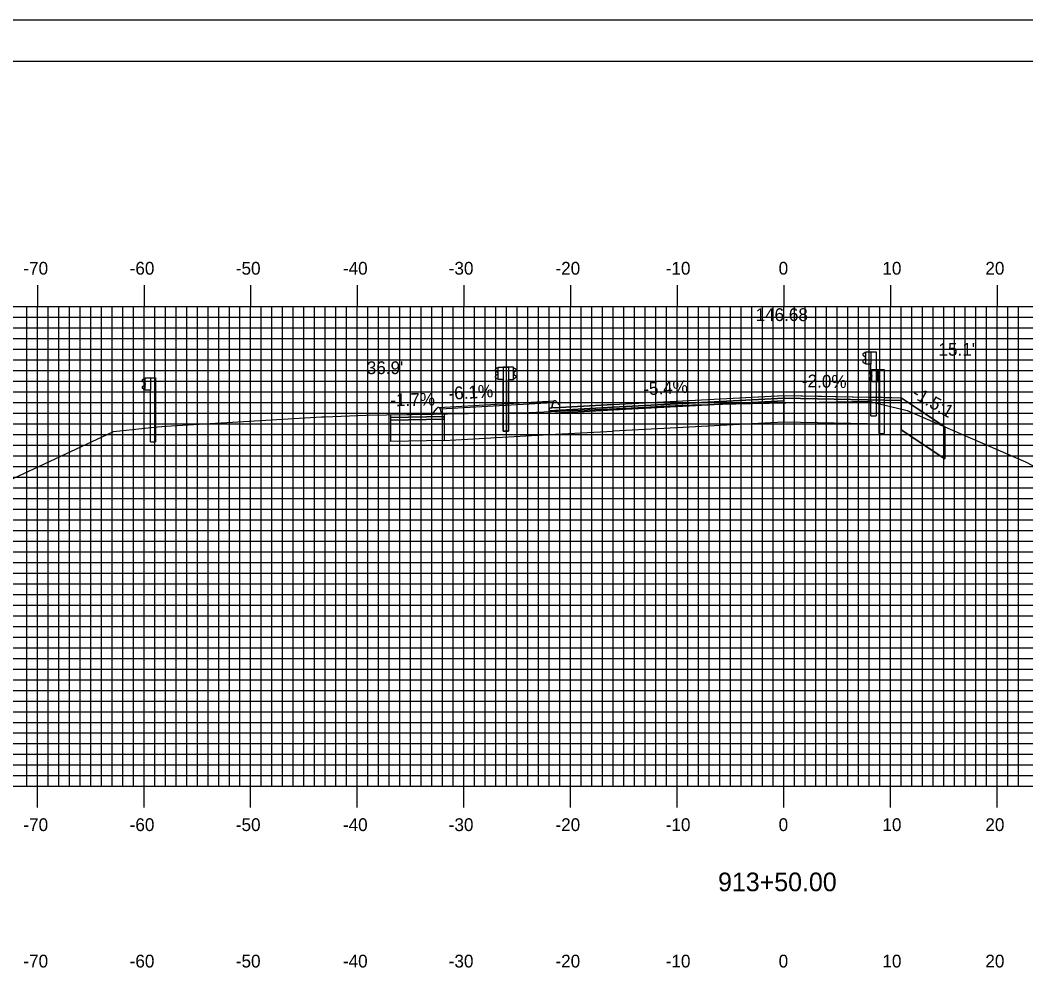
# Model space of a CAD drawing. Extents: x 860258 to 860601, y 364765 to 364985.
# Drawn here: x 860352.3 to 860446.6, y 364895.8 to 364985.2 of the extents above; entities that cross this region are included whole.
import ezdxf

# ---------------------------------------------------------------- set-up
doc = ezdxf.new("R2010")
doc.units = 0
for name, color, linetype in [('ANNOTATION', 7, 'Continuous'), ('BORDER', 7, 'Continuous'), ('D_Curb_Type_3M2_Lt', 7, 'Continuous'), ('D_Curb_Type_3M2_Rt', 7, 'Continuous'), ('D_Guardrail_Beam_Rt', 7, 'Continuous'), ('D_Roadway_Centerline', 7, 'Continuous'), ('D_Roadway_Centerline_Text', 7, 'Continuous'), ('D_Roadway_Edge_Shoulder', 7, 'Continuous'), ('D_Roadway_Edge_TW', 7, 'Continuous'), ('D_Roadway_FinishedGrade', 7, 'Continuous'), ('D_Roadway_Pavement', 7, 'Continuous'), ('D_Roadway_SubGrade', 7, 'Continuous'), ('D_Text_Standard', 7, 'Continuous'), ('H_V ANNOTATION', 7, 'Continuous'), ('M_Guardrail', 7, 'Continuous'), ('M_Roadway_Centerline', 7, 'Continuous'), ('MAJOR', 7, 'Continuous'), ('MINOR', 7, 'Continuous'), ('PATTERNING', 7, 'Continuous'), ('PLOT BOUNDARY', 7, 'Continuous'), ('S_Roadway_Centerline', 7, 'Continuous')]:
    doc.layers.add(name, color=color, linetype=linetype)

msp = doc.modelspace()

# ---------------------------------------------------------------- linework, layer by layer
at = {"layer": 'BORDER'}
msp.add_lwpolyline([(860274.299, 364771.302), (860594.299, 364771.302), (860594.299, 364981.302), (860274.299, 364981.302)], close=True, dxfattribs=at)
at = {"layer": 'D_Curb_Type_3M2_Lt'}
for p, q in [((860402.258, 364949.339), (860402.15, 364948.845)), ((860402.15, 364948.845), (860402.9, 364948.845)), ((860402.394, 364949.468), (860402.398, 364949.468)), ((860402.9, 364949.012), (860402.545, 364949.414)), ((860402.9, 364948.845), (860402.9, 364949.012))]:
    msp.add_line(p, q, dxfattribs=at)
msp.add_arc((860402.42, 364949.304), 0.167, 41.38705, 167.66476, dxfattribs=at)
at = {"layer": 'D_Curb_Type_3M2_Rt'}
for p, q in [((860391.036, 364948.385), (860391.39, 364948.787)), ((860391.678, 364948.712), (860391.786, 364948.218)), ((860391.036, 364948.218), (860391.036, 364948.385)), ((860391.786, 364948.218), (860391.036, 364948.218))]:
    msp.add_line(p, q, dxfattribs=at)
msp.add_arc((860391.515, 364948.677), 0.167, 12.33524, 138.61295, dxfattribs=at)
at = {"layer": 'D_Guardrail_Beam_Rt'}
for p, q in [((860432.17, 364952.403), (860432.857, 364952.403)), ((860432.17, 364951.236), (860432.17, 364952.403)), ((860432.691, 364952.403), (860432.691, 364951.236)), ((860432.795, 364952.403), (860432.795, 364951.236)), ((860432.857, 364952.403), (860433.328, 364952.403)), ((860432.857, 364952.403), (860432.857, 364951.236)), ((860433.328, 364952.403), (860433.328, 364946.403)), ((860432.08, 364952.298), (860431.936, 364952.198)), ((860431.936, 364952.055), (860432.132, 364951.919)), ((860432.132, 364951.72), (860431.936, 364951.584)), ((860431.936, 364951.44), (860432.08, 364951.34)), ((860432.17, 364952.319), (860432.096, 364952.305)), ((860432.166, 364951.854), (860432.166, 364951.784)), ((860432.096, 364951.334), (860432.17, 364951.319)), ((860432.857, 364951.236), (860432.17, 364951.236)), ((860432.837, 364946.403), (860432.837, 364951.236)), ((860432.837, 364946.403), (860433.328, 364946.403))]:
    msp.add_line(p, q, dxfattribs=at)
for centre, major_axis, start_param, end_param in [((860431.987, 364952.126), (-0.0877, 0), 5.323254, 7.243116), ((860431.987, 364951.512), (-0.0877, 0), 5.323254, 7.243116), ((860432.104, 364952.264), (-0.0417, 0), 4.907132, 5.323254), ((860432.087, 364951.854), (0.0789, 0), 0, 0.959931), ((860432.087, 364951.784), (0.0789, 0), 5.323254, 6.283185), ((860432.104, 364951.374), (-0.0417, 0), 0.959931, 1.376053)]:
    msp.add_ellipse(centre, major_axis=major_axis, ratio=0.995501, start_param=start_param, end_param=end_param, dxfattribs=at)
at = {"layer": 'D_Roadway_Centerline'}
for points in [[(860402.9, 364948.845), (860407.898, 364949.115), (860407.899, 364949.115), (860423.887, 364949.979), (860423.9, 364949.979), (860427.436, 364949.908), (860431.899, 364949.819), (860431.9, 364949.819), (860433.145, 364949.794), (860434.9, 364949.759), (860434.906, 364949.756), (860438.999, 364947.028)], [(860387.035, 364948.15), (860390.957, 364948.217), (860391.034, 364948.218), (860391.036, 364948.218)]]:
    msp.add_lwpolyline(points, dxfattribs=at)
at = {"layer": 'D_Roadway_Edge_Shoulder'}
for points in [[(860423.9, 364949.979), (860431.899, 364949.819), (860431.899, 364949.819), (860434.9, 364949.759), (860434.9, 364949.509), (860423.9, 364949.729)], [(860407.899, 364949.115), (860402.9, 364948.845), (860401.9, 364948.791), (860401.9, 364948.541), (860407.899, 364948.865)], [(860387.035, 364948.15), (860391.036, 364948.218), (860392.036, 364948.236), (860392.036, 364947.986), (860387.035, 364947.9)]]:
    msp.add_lwpolyline(points, close=True, dxfattribs=at)
at = {"layer": 'D_Roadway_Edge_TW'}
msp.add_lwpolyline([(860407.899, 364949.115), (860423.9, 364949.979), (860423.9, 364949.729), (860407.899, 364948.865)], close=True, dxfattribs=at)
at = {"layer": 'D_Roadway_FinishedGrade'}
msp.add_line((860434.906, 364949.756), (860434.906, 364946.756), dxfattribs=at)
for points in [[(860434.906, 364949.756), (860436.406, 364948.756), (860438.999, 364947.028)], [(860391.557, 364948.838), (860402.379, 364949.465)], [(860438.999, 364947.028), (860438.999, 364944.028), (860434.906, 364946.756)]]:
    msp.add_lwpolyline(points, dxfattribs=at)
at = {"layer": 'D_Roadway_Pavement'}
for points in [[(860407.899, 364948.865), (860423.9, 364949.729), (860423.9, 364949.479), (860407.899, 364948.615)], [(860407.899, 364948.865), (860401.9, 364948.541), (860401.9, 364948.291), (860407.899, 364948.615)], [(860387.035, 364947.9), (860392.036, 364947.986), (860392.036, 364947.736), (860387.035, 364947.65)]]:
    msp.add_lwpolyline(points, close=True, dxfattribs=at)
msp.add_lwpolyline([(860423.9, 364949.729), (860423.9, 364949.479)], dxfattribs=at)
msp.add_lwpolyline([(860423.9, 364949.729), (860423.9, 364949.479)], dxfattribs=at)
at = {"layer": 'D_Roadway_SubGrade'}
for points in [[(860423.9, 364949.479), (860423.9, 364949.729), (860434.9, 364949.509), (860434.9, 364949.759), (860434.906, 364947.259), (860423.9, 364947.479)], [(860392.036, 364948.236), (860392.036, 364945.736), (860401.9, 364946.291), (860401.9, 364948.291), (860401.9, 364948.541), (860401.9, 364948.791), (860402.141, 364948.804), (860402.247, 364949.29), (860391.685, 364948.678), (860391.784, 364948.232)], [(860407.899, 364948.615), (860401.9, 364948.291), (860401.9, 364948.541), (860401.9, 364946.291), (860407.899, 364946.615)], [(860407.899, 364948.615), (860423.9, 364949.479), (860423.9, 364947.479), (860407.899, 364946.615)], [(860387.035, 364947.65), (860392.036, 364947.736), (860392.036, 364947.986), (860392.036, 364945.736), (860387.035, 364945.65)]]:
    msp.add_lwpolyline(points, close=True, dxfattribs=at)
at = {"layer": 'M_Guardrail'}
for p, q in [((860431.486, 364953.978), (860431.343, 364953.878)), ((860431.343, 364953.735), (860431.538, 364953.598)), ((860431.538, 364953.379), (860431.343, 364953.242)), ((860431.585, 364953.999), (860431.503, 364953.985)), ((860431.572, 364953.534), (860431.572, 364953.443)), ((860431.585, 364954.072), (860432.075, 364954.072)), ((860431.585, 364952.905), (860431.585, 364954.072)), ((860432.075, 364954.072), (860432.566, 364954.072)), ((860432.075, 364954.072), (860432.075, 364952.905)), ((860432.566, 364954.072), (860432.566, 364948.072)), ((860396.998, 364952.53), (860396.854, 364952.43)), ((860397.097, 364952.551), (860397.015, 364952.537)), ((860397.097, 364952.624), (860397.586, 364952.624)), ((860397.097, 364951.458), (860397.097, 364952.624)), ((860397.575, 364952.622), (860397.575, 364946.622)), ((860398.066, 364952.622), (860397.575, 364952.622)), ((860397.586, 364952.624), (860398.078, 364952.624)), ((860397.586, 364952.624), (860397.586, 364951.458)), ((860398.556, 364952.622), (860398.066, 364952.622)), ((860398.066, 364952.622), (860398.066, 364951.455)), ((860398.078, 364952.624), (860398.078, 364946.624)), ((860398.556, 364951.455), (860398.556, 364952.622)), ((860398.556, 364952.549), (860398.638, 364952.534)), ((860398.655, 364952.528), (860398.798, 364952.428)), ((860431.343, 364953.099), (860431.486, 364952.999)), ((860431.503, 364952.993), (860431.585, 364952.978)), ((860432.075, 364952.905), (860431.585, 364952.905)), ((860432.075, 364948.072), (860432.075, 364952.905)), ((860363.908, 364951.533), (860363.765, 364951.433)), ((860364.007, 364951.555), (860363.925, 364951.54)), ((860364.007, 364951.628), (860364.496, 364951.628)), ((860364.007, 364950.461), (860364.007, 364951.628)), ((860364.496, 364951.628), (860364.988, 364951.628)), ((860364.496, 364951.628), (860364.496, 364950.461)), ((860364.988, 364951.628), (860364.988, 364945.628)), ((860396.854, 364952.287), (860397.05, 364952.151)), ((860397.05, 364951.931), (860396.854, 364951.795)), ((860396.854, 364951.652), (860396.998, 364951.552)), ((860397.015, 364951.545), (860397.097, 364951.531)), ((860397.083, 364952.087), (860397.083, 364951.995)), ((860397.586, 364951.458), (860397.097, 364951.458)), ((860397.586, 364946.624), (860397.586, 364951.458)), ((860398.066, 364946.622), (860398.066, 364951.455)), ((860398.066, 364951.455), (860398.556, 364951.455)), ((860398.638, 364951.542), (860398.556, 364951.528)), ((860398.569, 364952.084), (860398.569, 364951.993)), ((860398.798, 364952.284), (860398.603, 364952.148)), ((860398.603, 364951.928), (860398.798, 364951.792)), ((860398.798, 364951.649), (860398.655, 364951.549)), ((860363.765, 364951.29), (860363.96, 364951.154)), ((860363.96, 364950.934), (860363.765, 364950.798)), ((860363.765, 364950.655), (860363.908, 364950.555)), ((860363.925, 364950.548), (860364.007, 364950.534)), ((860363.994, 364951.09), (860363.994, 364950.999)), ((860364.496, 364950.461), (860364.007, 364950.461)), ((860364.496, 364945.628), (860364.496, 364950.461)), ((860432.075, 364948.072), (860432.566, 364948.072)), ((860398.066, 364946.622), (860397.575, 364946.622)), ((860397.586, 364946.624), (860398.078, 364946.624)), ((860364.496, 364945.628), (860364.988, 364945.628))]:
    msp.add_line(p, q, dxfattribs=at)
for centre, major_axis, start_param, end_param in [((860431.393, 364953.806), (-0.0877, 0), 5.323254, 7.243116), ((860431.51, 364953.944), (-0.0417, 0), 4.886922, 5.323254), ((860431.493, 364953.534), (0.0789, 0), 0, 0.959931), ((860431.493, 364953.443), (0.0789, 0), 5.323254, 6.283185), ((860396.905, 364952.359), (-0.0877, 0), 5.323254, 7.243116), ((860397.022, 364952.496), (-0.0417, 0), 4.886922, 5.323254), ((860398.631, 364952.494), (0.0417, 0), 0.959931, 1.396263), ((860398.748, 364952.356), (0.0877, 0), 5.323254, 7.243116), ((860431.393, 364953.171), (-0.0877, 0), 5.323254, 7.243116), ((860431.51, 364953.033), (-0.0417, 0), 0.959931, 1.396263), ((860363.815, 364951.362), (-0.0877, 0), 5.323254, 7.243116), ((860363.932, 364951.499), (-0.0417, 0), 4.886922, 5.323254), ((860396.905, 364951.723), (-0.0877, 0), 5.323254, 7.243116), ((860397.022, 364951.586), (-0.0417, 0), 0.959931, 1.396263), ((860397.005, 364952.087), (0.0789, 0), 0, 0.959931), ((860397.005, 364951.995), (0.0789, 0), 5.323254, 6.283185), ((860398.648, 364952.084), (-0.0789, 0), 5.323254, 6.283185), ((860398.648, 364951.993), (-0.0789, 0), 6.283185, 7.243116), ((860398.631, 364951.583), (0.0417, 0), 4.886922, 5.323254), ((860398.748, 364951.721), (0.0877, 0), 5.323254, 7.243116), ((860363.815, 364950.727), (-0.0877, 0), 5.323254, 7.243116), ((860363.932, 364950.589), (-0.0417, 0), 0.959931, 1.396263), ((860363.915, 364951.09), (0.0789, 0), 0, 0.959931), ((860363.915, 364950.999), (0.0789, 0), 5.323254, 6.283185)]:
    msp.add_ellipse(centre, major_axis=major_axis, ratio=0.995501, start_param=start_param, end_param=end_param, dxfattribs=at)
at = {"layer": 'MAJOR'}
for p, q in [((860353.899, 364960.306), (860353.899, 364958.302)), ((860363.899, 364960.306), (860363.899, 364958.302)), ((860373.899, 364960.306), (860373.899, 364958.302)), ((860383.899, 364960.306), (860383.899, 364958.302)), ((860393.899, 364960.306), (860393.899, 364958.302)), ((860403.899, 364960.306), (860403.899, 364958.302)), ((860413.899, 364960.306), (860413.899, 364958.302)), ((860423.899, 364960.306), (860423.899, 364958.302)), ((860433.899, 364960.306), (860433.899, 364958.302)), ((860443.899, 364960.306), (860443.899, 364958.302)), ((860283.899, 364958.302), (860563.899, 364958.302)), ((860283.899, 364958.302), (860563.899, 364958.302)), ((860353.899, 364913.302), (860353.899, 364958.302)), ((860363.899, 364913.302), (860363.899, 364958.302)), ((860373.899, 364913.302), (860373.899, 364958.302)), ((860383.899, 364913.302), (860383.899, 364958.302)), ((860393.899, 364913.302), (860393.899, 364958.302)), ((860403.899, 364913.302), (860403.899, 364958.302)), ((860413.899, 364913.302), (860413.899, 364958.302)), ((860423.899, 364913.302), (860423.899, 364958.302)), ((860433.899, 364913.302), (860433.899, 364958.302)), ((860443.899, 364913.302), (860443.899, 364958.302)), ((860283.899, 364953.302), (860563.899, 364953.302)), ((860283.899, 364948.302), (860563.899, 364948.302)), ((860283.899, 364943.302), (860563.899, 364943.302)), ((860283.899, 364938.302), (860563.899, 364938.302)), ((860283.899, 364933.302), (860563.899, 364933.302)), ((860283.899, 364928.302), (860563.899, 364928.302)), ((860283.899, 364923.302), (860563.899, 364923.302)), ((860283.899, 364918.302), (860563.899, 364918.302)), ((860283.899, 364913.302), (860563.899, 364913.302)), ((860283.899, 364913.302), (860563.899, 364913.302)), ((860353.899, 364911.298), (860353.899, 364913.302)), ((860363.899, 364911.298), (860363.899, 364913.302)), ((860373.899, 364911.298), (860373.899, 364913.302)), ((860383.899, 364911.298), (860383.899, 364913.302)), ((860393.899, 364911.298), (860393.899, 364913.302)), ((860403.899, 364911.298), (860403.899, 364913.302)), ((860413.899, 364911.298), (860413.899, 364913.302)), ((860423.899, 364911.298), (860423.899, 364913.302)), ((860433.899, 364911.298), (860433.899, 364913.302)), ((860443.899, 364911.298), (860443.899, 364913.302))]:
    msp.add_line(p, q, dxfattribs=at)
at = {"layer": 'MINOR'}
for p, q in [((860352.899, 364913.302), (860352.899, 364958.302)), ((860354.899, 364913.302), (860354.899, 364958.302)), ((860355.899, 364913.302), (860355.899, 364958.302)), ((860356.899, 364913.302), (860356.899, 364958.302)), ((860357.899, 364913.302), (860357.899, 364958.302)), ((860358.899, 364913.302), (860358.899, 364958.302)), ((860359.899, 364913.302), (860359.899, 364958.302)), ((860360.899, 364913.302), (860360.899, 364958.302)), ((860361.899, 364913.302), (860361.899, 364958.302)), ((860362.899, 364913.302), (860362.899, 364958.302)), ((860364.899, 364913.302), (860364.899, 364958.302)), ((860365.899, 364913.302), (860365.899, 364958.302)), ((860366.899, 364913.302), (860366.899, 364958.302)), ((860367.899, 364913.302), (860367.899, 364958.302)), ((860368.899, 364913.302), (860368.899, 364958.302)), ((860369.899, 364913.302), (860369.899, 364958.302)), ((860370.899, 364913.302), (860370.899, 364958.302)), ((860371.899, 364913.302), (860371.899, 364958.302)), ((860372.899, 364913.302), (860372.899, 364958.302)), ((860374.899, 364913.302), (860374.899, 364958.302)), ((860375.899, 364913.302), (860375.899, 364958.302)), ((860376.899, 364913.302), (860376.899, 364958.302)), ((860377.899, 364913.302), (860377.899, 364958.302)), ((860378.899, 364913.302), (860378.899, 364958.302)), ((860379.899, 364913.302), (860379.899, 364958.302)), ((860380.899, 364913.302), (860380.899, 364958.302)), ((860381.899, 364913.302), (860381.899, 364958.302)), ((860382.899, 364913.302), (860382.899, 364958.302)), ((860384.899, 364913.302), (860384.899, 364958.302)), ((860385.899, 364913.302), (860385.899, 364958.302)), ((860386.899, 364913.302), (860386.899, 364958.302)), ((860387.899, 364913.302), (860387.899, 364958.302)), ((860388.899, 364913.302), (860388.899, 364958.302)), ((860389.899, 364913.302), (860389.899, 364958.302)), ((860390.899, 364913.302), (860390.899, 364958.302)), ((860391.899, 364913.302), (860391.899, 364958.302)), ((860392.899, 364913.302), (860392.899, 364958.302)), ((860394.899, 364913.302), (860394.899, 364958.302)), ((860395.899, 364913.302), (860395.899, 364958.302)), ((860396.899, 364913.302), (860396.899, 364958.302)), ((860397.899, 364913.302), (860397.899, 364958.302)), ((860398.899, 364913.302), (860398.899, 364958.302)), ((860399.899, 364913.302), (860399.899, 364958.302)), ((860400.899, 364913.302), (860400.899, 364958.302)), ((860401.899, 364913.302), (860401.899, 364958.302)), ((860402.899, 364913.302), (860402.899, 364958.302)), ((860404.899, 364913.302), (860404.899, 364958.302)), ((860405.899, 364913.302), (860405.899, 364958.302)), ((860406.899, 364913.302), (860406.899, 364958.302)), ((860407.899, 364913.302), (860407.899, 364958.302)), ((860408.899, 364913.302), (860408.899, 364958.302)), ((860409.899, 364913.302), (860409.899, 364958.302)), ((860410.899, 364913.302), (860410.899, 364958.302)), ((860411.899, 364913.302), (860411.899, 364958.302)), ((860412.899, 364913.302), (860412.899, 364958.302)), ((860414.899, 364913.302), (860414.899, 364958.302)), ((860415.899, 364913.302), (860415.899, 364958.302)), ((860416.899, 364913.302), (860416.899, 364958.302)), ((860417.899, 364913.302), (860417.899, 364958.302)), ((860418.899, 364913.302), (860418.899, 364958.302)), ((860419.899, 364913.302), (860419.899, 364958.302)), ((860420.899, 364913.302), (860420.899, 364958.302)), ((860421.899, 364913.302), (860421.899, 364958.302)), ((860422.899, 364913.302), (860422.899, 364958.302)), ((860424.899, 364913.302), (860424.899, 364958.302)), ((860425.899, 364913.302), (860425.899, 364958.302)), ((860426.899, 364913.302), (860426.899, 364958.302)), ((860427.899, 364913.302), (860427.899, 364958.302)), ((860428.899, 364913.302), (860428.899, 364958.302)), ((860429.899, 364913.302), (860429.899, 364958.302)), ((860430.899, 364913.302), (860430.899, 364958.302)), ((860431.899, 364913.302), (860431.899, 364958.302)), ((860432.899, 364913.302), (860432.899, 364958.302)), ((860434.899, 364913.302), (860434.899, 364958.302)), ((860435.899, 364913.302), (860435.899, 364958.302)), ((860436.899, 364913.302), (860436.899, 364958.302)), ((860437.899, 364913.302), (860437.899, 364958.302)), ((860438.899, 364913.302), (860438.899, 364958.302)), ((860439.899, 364913.302), (860439.899, 364958.302)), ((860440.899, 364913.302), (860440.899, 364958.302)), ((860441.899, 364913.302), (860441.899, 364958.302)), ((860442.899, 364913.302), (860442.899, 364958.302)), ((860444.899, 364913.302), (860444.899, 364958.302)), ((860445.899, 364913.302), (860445.899, 364958.302)), ((860283.899, 364957.302), (860563.899, 364957.302)), ((860283.899, 364956.302), (860563.899, 364956.302)), ((860283.899, 364955.302), (860563.899, 364955.302)), ((860283.899, 364954.302), (860563.899, 364954.302)), ((860283.899, 364952.302), (860563.899, 364952.302)), ((860283.899, 364951.302), (860563.899, 364951.302)), ((860283.899, 364950.302), (860563.899, 364950.302)), ((860283.899, 364949.302), (860563.899, 364949.302)), ((860283.899, 364947.302), (860563.899, 364947.302)), ((860283.899, 364946.302), (860563.899, 364946.302)), ((860283.899, 364945.302), (860563.899, 364945.302)), ((860283.899, 364944.302), (860563.899, 364944.302)), ((860283.899, 364942.302), (860563.899, 364942.302)), ((860283.899, 364941.302), (860563.899, 364941.302)), ((860283.899, 364940.302), (860563.899, 364940.302)), ((860283.899, 364939.302), (860563.899, 364939.302)), ((860283.899, 364937.302), (860563.899, 364937.302)), ((860283.899, 364936.302), (860563.899, 364936.302)), ((860283.899, 364935.302), (860563.899, 364935.302)), ((860283.899, 364934.302), (860563.899, 364934.302)), ((860283.899, 364932.302), (860563.899, 364932.302)), ((860283.899, 364931.302), (860563.899, 364931.302)), ((860283.899, 364930.302), (860563.899, 364930.302)), ((860283.899, 364929.302), (860563.899, 364929.302)), ((860283.899, 364927.302), (860563.899, 364927.302)), ((860283.899, 364926.302), (860563.899, 364926.302)), ((860283.899, 364925.302), (860563.899, 364925.302)), ((860283.899, 364924.302), (860563.899, 364924.302)), ((860283.899, 364922.302), (860563.899, 364922.302)), ((860283.899, 364921.302), (860563.899, 364921.302)), ((860283.899, 364920.302), (860563.899, 364920.302)), ((860283.899, 364919.302), (860563.899, 364919.302)), ((860283.899, 364917.302), (860563.899, 364917.302)), ((860283.899, 364916.302), (860563.899, 364916.302)), ((860283.899, 364915.302), (860563.899, 364915.302)), ((860283.899, 364914.302), (860563.899, 364914.302))]:
    msp.add_line(p, q, dxfattribs=at)
at = {"layer": 'PATTERNING'}
for points in [[(860438.999, 364947.028), (860436.406, 364948.756), (860434.906, 364949.756)], [(860434.906, 364949.756), (860434.906, 364947.259), (860434.906, 364946.756)], [(860434.906, 364946.756), (860438.999, 364944.028), (860438.999, 364947.028)]]:
    msp.add_lwpolyline(points, dxfattribs=at)
at = {"layer": 'PLOT BOUNDARY'}
msp.add_lwpolyline([(860258.113, 364765.184), (860598.113, 364765.184), (860598.113, 364985.184), (860258.113, 364985.184)], close=True, dxfattribs=at)
at = {"layer": 'S_Roadway_Centerline'}
msp.add_lwpolyline([(860344.239, 364938.746), (860360.971, 364946.563), (860361.042, 364946.597), (860365.157, 364947.03), (860365.982, 364947.097), (860369.562, 364947.313), (860380.548, 364947.973), (860380.823, 364947.96), (860384.725, 364948.11), (860400.009, 364948.373), (860409.579, 364948.808), (860410.842, 364948.884), (860412.36, 364948.976), (860414.366, 364949.043), (860415.323, 364949.075), (860416.931, 364949.123), (860419.406, 364949.168), (860431.893, 364949.423), (860432.209, 364949.349), (860435.477, 364948.548), (860446.579, 364943.755), (860452.104, 364940.822)], dxfattribs=at)

# ---------------------------------------------------------------- texts
at = {"layer": 'ANNOTATION'}
for s, rotation, p in [('-2.0%', 358.85415, (860425.586, 364950.746)), ('-6.1%', 3.49979, (860392.488, 364949.552)), ('-5.4%', 3.09093, (860410.746, 364949.98)), ('-1.7%', 0.98138, (860387.004, 364948.949)), ('-1.5:1', 330.177, (860435.827, 364949.853))]:
    msp.add_text(s, height=1.2, rotation=rotation, dxfattribs=at).set_placement(p)
at = {"layer": 'D_Roadway_Centerline_Text'}
msp.add_text('146.68', height=1.2, dxfattribs=at).set_placement((860421.251, 364956.951))
at = {"layer": 'D_Text_Standard'}
for s, p in [("15.1'", (860438.41, 364953.702)), ("36.9'", (860384.79, 364951.971))]:
    msp.add_text(s, height=1.2, dxfattribs=at).set_placement(p)
at = {"layer": 'H_V ANNOTATION'}
for s, height, p in [('-70', 1.2, (860352.583, 364961.302)), ('-60', 1.2, (860362.551, 364961.302)), ('-50', 1.2, (860372.508, 364961.302)), ('-40', 1.2, (860382.551, 364961.302)), ('-30', 1.2, (860392.476, 364961.302)), ('-20', 1.2, (860402.486, 364961.302)), ('-10', 1.2, (860412.829, 364961.302)), ('0', 1.2, (860423.417, 364961.302)), ('10', 1.2, (860433.15, 364961.302)), ('20', 1.2, (860442.807, 364961.302)), ('-70', 1.2, (860352.583, 364909.102)), ('-60', 1.2, (860362.551, 364909.102)), ('-50', 1.2, (860372.508, 364909.102)), ('-40', 1.2, (860382.551, 364909.102)), ('-30', 1.2, (860392.476, 364909.102)), ('-20', 1.2, (860402.486, 364909.102)), ('-10', 1.2, (860412.829, 364909.102)), ('0', 1.2, (860423.417, 364909.102)), ('10', 1.2, (860433.15, 364909.102)), ('20', 1.2, (860442.807, 364909.102)), ('913+50.00', 1.75, (860417.735, 364903.458)), ('-70', 1.2, (860352.583, 364896.302)), ('-60', 1.2, (860362.551, 364896.302)), ('-50', 1.2, (860372.508, 364896.302)), ('-40', 1.2, (860382.551, 364896.302)), ('-30', 1.2, (860392.476, 364896.302)), ('-20', 1.2, (860402.486, 364896.302)), ('-10', 1.2, (860412.829, 364896.302)), ('0', 1.2, (860423.417, 364896.302)), ('10', 1.2, (860433.15, 364896.302)), ('20', 1.2, (860442.807, 364896.302))]:
    msp.add_text(s, height=height, dxfattribs=at).set_placement(p)
at = {"layer": 'M_Roadway_Centerline'}
for s, p in [('C', (860412.354, 364948.976)), ('L', (860412.36, 364948.968)), ('C', (860380.543, 364947.973)), ('L', (860380.548, 364947.965))]:
    msp.add_text(s, height=0.0146, dxfattribs=at).set_placement(p)

doc.saveas('drawing.dxf')
